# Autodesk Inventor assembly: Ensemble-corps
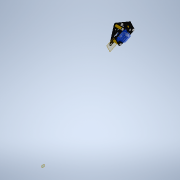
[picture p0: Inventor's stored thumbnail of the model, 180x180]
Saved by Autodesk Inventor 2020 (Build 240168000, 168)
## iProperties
Created: 2021-10
Part Number: Ensemble-corps
Document SubType Name: Assembly
Designer: bruno
Mass: 9.22633 g
Surface Area: 139.573 cm^2
Volume: 5.93462 cm^3
Density: 1.55466 g/cm^3
Author: bruno
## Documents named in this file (6)
- C:\Users\bruno\OneDrive\Bureau\Robot-Inventor\Robot-equilibrage\Ensemble-corps.iam
- C:\Users\bruno\OneDrive\Bureau\Robot-Inventor\Robot-equilibrage\Ensemble-support-servo.iam
- C:\Users\bruno\OneDrive\Bureau\Robot-Inventor\Robot-equilibrage\Servo\Servo.iam
- C:\Users\bruno\OneDrive\Bureau\Robot-Inventor\Robot-equilibrage\ecrou-hexa.ipt
- C:\Users\bruno\OneDrive\Bureau\Robot-Inventor\Robot-equilibrage\plaque-triangle.ipt
- C:\Users\bruno\Documents\Inventor\Content Center Files\R2020\fr-FR\ANSI B18.6.7M(01)\ANSI B18.6.7M - M3x0,5 x 5(5).ipt
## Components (12 placed, 5 different names)
1. Ensemble-support-servo:1 [sub-assembly] — Placage:1, Logement:1, Logement:2, Logement:3, Placage:5, Placage:6, Placage:7, Angle:1, Placage:10, Placage:13
2. Servo:1 [sub-assembly] — Placage:1, Placage:5
3. ecrou-hexa:1 — Logement:3, Placage:12, Placage:16
4. ecrou-hexa:2 — Logement:1, Placage:8, Placage:9, Placage:15
5. ecrou-hexa:3 — Logement:2, Placage:11, Placage:14
6. plaque-triangle:1 — Placage:8, Placage:9, Angle:1, Placage:17, Placage:18, Placage:19
7. Vis à tête tronconique à empreinte cruciforme - Type IA - Métrique M3x0,5 x 5:1 — Placage:6, Placage:7
8. Vis à tête tronconique à empreinte cruciforme - Type IA - Métrique M3x0,5 x 5:2 — Placage:10, Placage:11
9. Vis à tête tronconique à empreinte cruciforme - Type IA - Métrique M3x0,5 x 5:3 — Placage:12, Placage:13
10. Vis à tête tronconique à empreinte cruciforme - Type IA - Métrique M3x0,5 x 5:4 — Placage:14, Placage:19
11. Vis à tête tronconique à empreinte cruciforme - Type IA - Métrique M3x0,5 x 5:5 — Placage:15, Placage:18
12. Vis à tête tronconique à empreinte cruciforme - Type IA - Métrique M3x0,5 x 5:6 — Placage:16, Placage:17
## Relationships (20: Mate 16, Insert 3, Angle 1)
- Placage:1 [Mate]: Ensemble-support-servo:1 ↔ Servo:1
- Logement:1 [Insert]: Ensemble-support-servo:1 ↔ ecrou-hexa:2
- Logement:2 [Insert]: Ensemble-support-servo:1 ↔ ecrou-hexa:3
- Logement:3 [Insert]: Ensemble-support-servo:1 ↔ ecrou-hexa:1
- Placage:5 [Mate]: Ensemble-support-servo:1 ↔ Servo:1
- Placage:6 [Mate]: Ensemble-support-servo:1 ↔ Vis à tête tronconique à empreinte cruciforme - Type IA - Métrique M3x0,5 x 5:1
- Placage:7 [Mate]: Ensemble-support-servo:1 ↔ Vis à tête tronconique à empreinte cruciforme - Type IA - Métrique M3x0,5 x 5:1
- Placage:8 [Mate]: ecrou-hexa:2 ↔ plaque-triangle:1
- Placage:9 [Mate]: ecrou-hexa:2 ↔ plaque-triangle:1
- Angle:1: Ensemble-support-servo:1 ↔ plaque-triangle:1
- Placage:10 [Mate]: Ensemble-support-servo:1 ↔ Vis à tête tronconique à empreinte cruciforme - Type IA - Métrique M3x0,5 x 5:2
- Placage:11 [Mate]: ecrou-hexa:3 ↔ Vis à tête tronconique à empreinte cruciforme - Type IA - Métrique M3x0,5 x 5:2
- Placage:12 [Mate]: ecrou-hexa:1 ↔ Vis à tête tronconique à empreinte cruciforme - Type IA - Métrique M3x0,5 x 5:3
- Placage:13 [Mate]: Ensemble-support-servo:1 ↔ Vis à tête tronconique à empreinte cruciforme - Type IA - Métrique M3x0,5 x 5:3
- Placage:14 [Mate]: ecrou-hexa:3 ↔ Vis à tête tronconique à empreinte cruciforme - Type IA - Métrique M3x0,5 x 5:4
- Placage:15 [Mate]: ecrou-hexa:2 ↔ Vis à tête tronconique à empreinte cruciforme - Type IA - Métrique M3x0,5 x 5:5
- Placage:16 [Mate]: ecrou-hexa:1 ↔ Vis à tête tronconique à empreinte cruciforme - Type IA - Métrique M3x0,5 x 5:6
- Placage:17 [Mate]: plaque-triangle:1 ↔ Vis à tête tronconique à empreinte cruciforme - Type IA - Métrique M3x0,5 x 5:6
- Placage:18 [Mate]: plaque-triangle:1 ↔ Vis à tête tronconique à empreinte cruciforme - Type IA - Métrique M3x0,5 x 5:5
- Placage:19 [Mate]: plaque-triangle:1 ↔ Vis à tête tronconique à empreinte cruciforme - Type IA - Métrique M3x0,5 x 5:4
